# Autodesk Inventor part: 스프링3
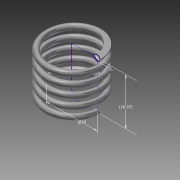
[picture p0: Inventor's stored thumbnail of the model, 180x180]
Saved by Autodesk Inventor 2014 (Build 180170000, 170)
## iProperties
Created: 2016-10
Part Number: 스프링3
Material: Steel, Carbon
Document SubType Name: Modeling
Designer: user
Mass: 6.81325 g
Surface Area: 17.664 cm^2
Volume: 0.865725 cm^3
Density: 7.87 g/cm^3
Appearance: Semi-Polished
Author: user
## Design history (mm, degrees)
sketch "Sketch1"
  geometry: L1 (0, 0)-(-9, 0); L2 (-9, 0)-(-9, -16.67); L3 (-9, -16.67)-(0, -16.67); L4 (0, -16.67)-(0, 0); C1 r 1 at (-9, 0)
  constraints: 8 end point, 2 parallel, 1 centre point, 1 coincident, 1 horizontal, 1 perpendicular
  dimensions: "d0" = 16.66987 distance of L1.end L2.end (derived); "d1" = 2 diameter of C1; "d2" = 18 diameter of L2 L4
coil "Coil1" pitch "d3" = 10; turns "d5" = 5; dims "d4" = 16.66987 (= d0), "d6" = 0, angle "d7" = 90 deg, angle "d8" = 90 deg, "d9" = 0, "d10" = 0
sketch "Sketch2"
  geometry: L1 (10, 0)-(8, 0) reference; L2 (10, 0)-(8, 0) reference; 1 further point
  constraints: 2 horizontal alignment
extrude "Extrusion1" cut sketch "Sketch2" stored distance "d11" = 10; taper "d12" = 0 deg
workplane "Work Plane1"
sketch "Sketch3"
  geometry: L1 (-1, 0)-(1, 0) reference; 1 further point
  constraints: 1 horizontal alignment
extrude "Extrusion2" cut sketch "Sketch3" stored distance "d14" = 10; taper "d15" = 0 deg
body "Solid1"
node "Project Cut Edges1"
node "Project Cut Edges2"
node "Project Cut Edges3"
other parameters: "d13" = 90 deg
